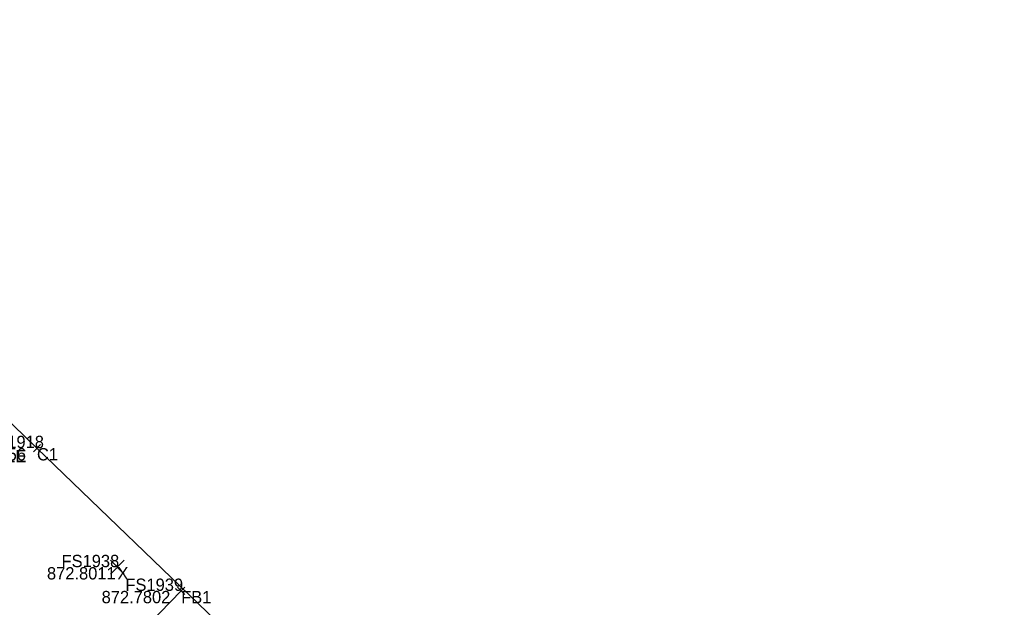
# Model space of a CAD drawing. Extents: x 1469677 to 1493262, y 375219 to 389293.
# Drawn here: x 1479592.9 to 1479688.4, y 380014.5 to 380071.8 of the extents above; entities that cross this region are included whole.
import ezdxf

# ---------------------------------------------------------------- set-up
doc = ezdxf.new("R2010")
doc.units = 0
for name, color, linetype in [('DV_X_Text', 7, 'Continuous'), ('GK_Visualization', 7, 'Continuous'), ('PNTELEV', 7, 'Continuous'), ('RD_P_Text', 7, 'Continuous'), ('RW_P_Esmt_SW', 7, 'Continuous'), ('RW_P_Esmt_U', 7, 'Continuous'), ('Text Property', 7, 'Continuous')]:
    doc.layers.add(name, color=color, linetype=linetype)

msp = doc.modelspace()

# ---------------------------------------------------------------- linework, layer by layer
at = {"layer": 'PNTELEV'}
for p, q in [((1479594.975, 380029.701), (1479594.255, 380030.395)), ((1479594.268, 380029.688), (1479594.962, 380030.408)), ((1479594.615, 380030.048), (1479594.615, 380030.048)), ((1479609.021, 380015.794), (1479608.303, 380016.489)), ((1479609.01, 380016.501), (1479608.314, 380015.782)), ((1479608.662, 380016.141), (1479608.662, 380016.141))]:
    msp.add_line(p, q, dxfattribs=at)
at = {"layer": 'RD_P_Text'}
msp.add_lwpolyline([(1479795.994, 380033.189), (1479773.609, 380022.189), (1479753.08, 380012.281), (1479732.582, 380002.187), (1479709.578, 379990.944), (1479686.038, 379979.568), (1479675.424, 379995.638), (1479673.845, 379997.042), (1479672.388, 379997.402), (1479671.072, 379997.477), (1479668.749, 379997.507), (1479666.577, 379997.444), (1479665.261, 379997.435), (1479663.761, 379996.907), (1479662.621, 379996.119), (1479646.813, 379979.589), (1479631.39, 379994.413), (1479612.948, 380012.394), (1479594.615, 380030.048), (1479574.047, 380049.976), (1479559.355, 380064.639), (1479550.33, 380073.358), (1479530.481, 380092.839), (1479523.351, 380099.688)], dxfattribs=at)
at = {"layer": 'RW_P_Esmt_U'}
for p, q in [((1479601.773, 380017.786), (1479603.107, 380019.121)), ((1479601.773, 380019.121), (1479603.107, 380017.786))]:
    msp.add_line(p, q, dxfattribs=at)
at = {"layer": 'Text Property'}
msp.add_lwpolyline([(1479608.662, 380016.141), (1479605.549, 380012.925), (1479630.214, 379989.527), (1479633.023, 379992.531)], dxfattribs=at)

# ---------------------------------------------------------------- texts
at = {"layer": 'DV_X_Text'}
for s, p in [('873.4256', (1479586.849, 380028.848)), ('872.8011', (1479595.588, 380017.253)), ('872.7802', (1479600.914, 380014.941))]:
    msp.add_text(s, height=1.2, dxfattribs=at).set_placement(p)
at = {"layer": 'GK_Visualization'}
for s, p in [('LPOLE', (1479588.409, 380028.677)), ('C1', (1479594.615, 380028.848)), ('X', (1479602.44, 380017.253)), ('FB1', (1479608.662, 380014.941))]:
    msp.add_text(s, height=1.2, dxfattribs=at).set_placement(p)
at = {"layer": 'RW_P_Esmt_SW'}
for s, p in [('FS1918', (1479589.675, 380030.048)), ('FS1938', (1479597.008, 380018.453)), ('FS1939', (1479603.23, 380016.141))]:
    msp.add_text(s, height=1.2, dxfattribs=at).set_placement(p)

doc.saveas('drawing.dxf')
